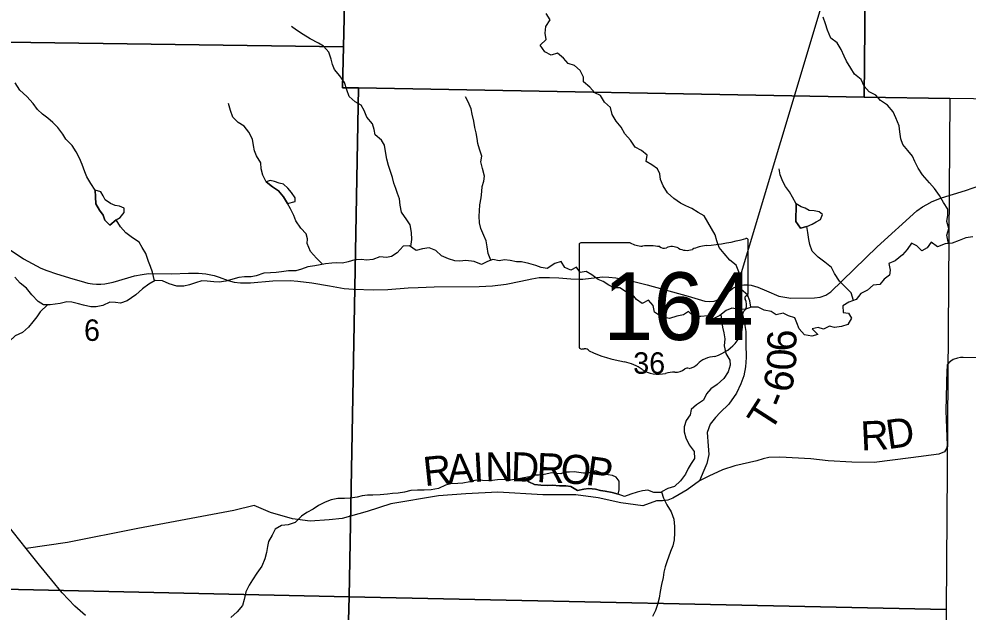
# Model space of a CAD drawing. Extents: x -3.6 to 34, y 0 to 32.8.
# Drawn here: x -0.41 to 1.441, y 27.961 to 29.117 of the extents above; entities that cross this region are included whole.
import ezdxf

# ---------------------------------------------------------------- set-up
doc = ezdxf.new("R2010")
doc.units = 0
for name, color, linetype in [('GM_X_Corporation', 7, 'Continuous'), ('GM_X_Minor_Lake', 7, 'Continuous'), ('GM_X_Minor_River', 7, 'Continuous'), ('GM_X_Section_Text', 7, 'Continuous'), ('GM_X_State_Location', 7, 'Continuous'), ('GM_X_State_Route', 7, 'Continuous'), ('GM_X_State_Shield', 7, 'Continuous'), ('GM_X_Township_Road', 7, 'Continuous'), ('GM_X_Township_Road_Text', 7, 'Continuous')]:
    doc.layers.add(name, color=color, linetype=linetype)

msp = doc.modelspace()

# ---------------------------------------------------------------- linework, layer by layer
at = {"layer": 'GM_X_Corporation'}
for points in [[(-0.7755, 30.0957), (0.2459, 30.0789), (0.244, 29.9924), (0.223, 29.0627), (-0.7627, 29.0764), (-0.7893, 29.0771)], [(1.2483, 29.9822), (1.2386, 28.9647), (0.2524, 28.9828), (0.2209, 28.9831), (0.223, 29.0627), (0.244, 29.9924)], [(2.2535, 29.9602), (2.2411, 28.9502), (1.4051, 28.9619), (1.2386, 28.9647), (1.2483, 29.9822)], [(-0.7627, 29.0764), (0.223, 29.0627), (0.2209, 28.9831), (0.2524, 28.9828), (0.2336, 27.9902), (-0.7925, 28.0131)], [(0.2524, 28.9828), (1.2386, 28.9647), (1.4051, 28.9619), (1.398, 27.966), (0.2336, 27.9902)], [(-0.7925, 28.0131), (0.2336, 27.9902), (0.2053, 26.9746), (-0.8131, 27.0015)], [(1.398, 27.966), (1.386, 26.9549), (0.2053, 26.9746), (0.2336, 27.9902)]]:
    msp.add_lwpolyline(points, close=True, dxfattribs=at)
at = {"layer": 'GM_X_Minor_Lake'}
for points in [[(0.1133, 28.7573), (0.1284, 28.7609), (0.1283, 28.7685), (0.1217, 28.779), (0.114, 28.7873), (0.1056, 28.7947), (0.0972, 28.7972), (0.0884, 28.8005), (0.0801, 28.8019), (0.0722, 28.7995)], [(-0.2617, 28.7834), (-0.2607, 28.7705), (-0.2605, 28.7565), (-0.2532, 28.7445), (-0.2458, 28.7347), (-0.2426, 28.7245), (-0.233, 28.7148), (-0.2203, 28.7253)], [(-0.2203, 28.7253), (-0.2128, 28.7303), (-0.2047, 28.7399), (-0.2052, 28.7479), (-0.2139, 28.7523), (-0.2227, 28.7537), (-0.2314, 28.757), (-0.2417, 28.7644), (-0.246, 28.7723), (-0.2507, 28.7798), (-0.2617, 28.7834)], [(0.0722, 28.7995), (0.0841, 28.7895), (0.0963, 28.7817), (0.1055, 28.7701), (0.1133, 28.7573)], [(1.1055, 28.7568), (1.1056, 28.7454), (1.1051, 28.7325), (1.1049, 28.7223), (1.1141, 28.7091), (1.1262, 28.7127)], [(1.1262, 28.7127), (1.1371, 28.7171), (1.145, 28.7214), (1.1529, 28.7264), (1.1573, 28.7356), (1.1507, 28.7408), (1.1405, 28.7433), (1.131, 28.7439), (1.123, 28.748), (1.1154, 28.7505), (1.1055, 28.7568)], [(0.7588, 28.1905), (0.7605, 28.1992), (0.7603, 28.2159), (0.7549, 28.2238), (0.7472, 28.2267), (0.7393, 28.2281), (0.7309, 28.2295), (0.7233, 28.2328), (0.7149, 28.2361), (0.7066, 28.2341), (0.6991, 28.2313), (0.6912, 28.2315), (0.6821, 28.2326), (0.673, 28.2339), (0.6639, 28.2334), (0.6548, 28.2333), (0.6465, 28.2301), (0.6386, 28.2311), (0.6291, 28.2321), (0.62, 28.2305), (0.6114, 28.2281), (0.6031, 28.2276), (0.594, 28.2278), (0.5857, 28.2246), (0.5744, 28.2226)], [(0.5744, 28.2226), (0.584, 28.2148), (0.5954, 28.2096), (0.6075, 28.2083), (0.62, 28.2077), (0.6306, 28.2079), (0.6442, 28.2066), (0.6567, 28.2071), (0.6662, 28.2058), (0.6792, 28.1976), (0.6913, 28.2004), (0.7015, 28.2014), (0.714, 28.2), (0.7238, 28.1975), (0.7333, 28.1965), (0.7466, 28.1937), (0.7588, 28.1905)]]:
    msp.add_lwpolyline(points, dxfattribs=at)
at = {"layer": 'GM_X_Minor_River'}
for points in [[(1.0172, 28.5549), (1.0156, 28.5673), (1.0109, 28.579), (0.9983, 28.5894), (0.9962, 28.6), (0.9945, 28.6133), (0.9936, 28.6239), (0.9885, 28.6371), (0.9766, 28.6471), (0.9654, 28.6595), (0.9558, 28.6715), (0.951, 28.6847), (0.9478, 28.696), (0.9408, 28.7088), (0.9335, 28.7208), (0.9261, 28.7332), (0.9143, 28.7395), (0.9024, 28.7473), (0.8902, 28.7528), (0.8803, 28.7579), (0.8673, 28.7672), (0.8546, 28.7784), (0.8465, 28.792), (0.8414, 28.8044), (0.8397, 28.8154), (0.8354, 28.8252), (0.8239, 28.8326), (0.8129, 28.8392), (0.8153, 28.8518), (0.8042, 28.8604), (0.7916, 28.8674), (0.7827, 28.8805), (0.7715, 28.8932), (0.7642, 28.906), (0.7549, 28.918), (0.7468, 28.9308), (0.7435, 28.9444), (0.732, 28.9548), (0.7239, 28.968), (0.7128, 28.9731), (0.7032, 28.984), (0.6909, 28.9944), (0.6908, 29.0039), (0.6841, 29.0163), (0.6734, 29.0264), (0.6612, 29.0304), (0.6516, 29.0405), (0.6401, 29.0502), (0.6281, 29.0462), (0.6158, 29.0532), (0.6062, 29.0663), (0.6178, 29.0771), (0.6164, 29.0893), (0.6174, 29.1022), (0.6259, 29.1156), (0.6181, 29.128)], [(1.4025, 28.6795), (1.3996, 28.6956), (1.4032, 28.7086), (1.3996, 28.7222), (1.4017, 28.7344), (1.4015, 28.7465), (1.393, 28.7593), (1.3852, 28.7728), (1.3752, 28.7863), (1.3659, 28.7979), (1.3521, 28.8129), (1.3436, 28.8264), (1.3373, 28.8392), (1.3326, 28.8498), (1.3237, 28.8606), (1.3137, 28.8726), (1.3098, 28.8832), (1.3077, 28.8972), (1.3064, 28.9085), (1.3004, 28.924), (1.2946, 28.9361), (1.2838, 28.9492), (1.2704, 28.9581), (1.2608, 28.9686), (1.2478, 28.9752), (1.2386, 28.986), (1.2323, 28.9989), (1.2193, 29.0097), (1.2123, 29.0213), (1.2038, 29.0345), (1.1995, 29.0443), (1.1936, 29.0578), (1.1854, 29.0706), (1.1732, 29.0799), (1.1669, 29.095), (1.1629, 29.1078), (1.1586, 29.1206)], [(0.3539, 28.6733), (0.3562, 28.6874), (0.3556, 28.701), (0.3527, 28.7154), (0.3461, 28.7256), (0.3357, 28.7406), (0.3332, 28.7538), (0.3319, 28.7667), (0.3279, 28.7765), (0.3248, 28.7863), (0.3212, 28.7969), (0.3184, 28.8078), (0.3152, 28.8176), (0.3108, 28.8312), (0.3072, 28.8437), (0.3048, 28.8584), (0.3027, 28.8709), (0.2968, 28.8807), (0.2846, 28.8911), (0.2829, 28.9017), (0.2793, 28.9127), (0.2685, 28.9258), (0.263, 28.9386), (0.2576, 28.9491), (0.2454, 28.9558), (0.2339, 28.9658), (0.2291, 28.9787), (0.2247, 28.993), (0.2155, 29.0065), (0.2054, 29.0185), (0.2015, 29.0283), (0.1987, 29.0385), (0.1943, 29.0525), (0.1835, 29.0641), (0.174, 29.0696), (0.1576, 29.0781), (0.1439, 29.0866), (0.1312, 29.0955), (0.1217, 29.1026)], [(-0.1456, 28.6063), (-0.1499, 28.6235), (-0.1539, 28.6345), (-0.1578, 28.6443), (-0.1629, 28.6598), (-0.1696, 28.6718), (-0.1754, 28.682), (-0.1888, 28.6905), (-0.2018, 28.7001), (-0.2122, 28.7121), (-0.2203, 28.7253), (-0.233, 28.7148), (-0.2426, 28.7245), (-0.2458, 28.7347), (-0.2532, 28.7445), (-0.2605, 28.7565), (-0.2607, 28.7705), (-0.2617, 28.7834), (-0.2699, 28.7966), (-0.278, 28.809), (-0.2819, 28.8188), (-0.2867, 28.8331), (-0.2922, 28.8459), (-0.2984, 28.858), (-0.3065, 28.8704), (-0.3185, 28.8827), (-0.3247, 28.8925), (-0.3343, 28.9056), (-0.3443, 28.9153), (-0.3539, 28.9235), (-0.3642, 28.9317), (-0.3742, 28.9406), (-0.3823, 28.9523), (-0.395, 28.9661), (-0.4085, 28.9781), (-0.4178, 28.9927)], [(0.182, 28.6388), (0.1702, 28.6508), (0.1586, 28.6639), (0.152, 28.679), (0.1526, 28.6885), (0.1502, 28.6983), (0.1398, 28.7095), (0.1301, 28.7234), (0.1258, 28.7336), (0.1195, 28.7471), (0.1133, 28.7573), (0.1055, 28.7701), (0.0963, 28.7817), (0.0841, 28.7895), (0.0722, 28.7995), (0.0652, 28.8127), (0.0623, 28.8252), (0.0614, 28.8369), (0.0532, 28.8501), (0.0493, 28.8602), (0.0476, 28.8705), (0.0456, 28.8829), (0.0382, 28.8961), (0.0293, 28.9081), (0.0171, 28.9155), (0.0067, 28.9256), (0.0023, 28.9384), (-0.0017, 28.9524)], [(0.51, 28.6465), (0.5053, 28.6601), (0.5028, 28.6726), (0.5008, 28.6843), (0.4968, 28.6952), (0.4909, 28.7088), (0.4881, 28.7197), (0.4875, 28.7326), (0.4881, 28.7429), (0.4887, 28.7547), (0.4915, 28.7684), (0.4925, 28.7809), (0.4935, 28.7904), (0.4963, 28.801), (0.4981, 28.8109), (0.4941, 28.8257), (0.4908, 28.8385), (0.4926, 28.8495), (0.4878, 28.8631), (0.4846, 28.8741), (0.4833, 28.8843), (0.4817, 28.8949), (0.4792, 28.9055), (0.4772, 28.9176), (0.4739, 28.9312), (0.4715, 28.9418), (0.466, 28.9553), (0.4605, 28.9651)], [(1.2174, 28.5682), (1.2129, 28.5828), (1.2025, 28.5936), (1.1899, 28.606), (1.1806, 28.6206), (1.1743, 28.6327), (1.1613, 28.6427), (1.1483, 28.6524), (1.1368, 28.6643), (1.1324, 28.6776), (1.1304, 28.6874), (1.1286, 28.701), (1.1262, 28.7127), (1.1141, 28.7091), (1.1049, 28.7223), (1.1051, 28.7325), (1.1056, 28.7454), (1.1055, 28.7568), (1.0988, 28.7696), (1.093, 28.7798), (1.0849, 28.7903), (1.0798, 28.8004), (1.0747, 28.8132), (1.0723, 28.8246)], [(1.4504, 28.6926), (1.4368, 28.6905), (1.4233, 28.685), (1.4097, 28.6802), (1.3961, 28.6789), (1.3815, 28.673), (1.3688, 28.6819), (1.3614, 28.6711), (1.3505, 28.6649), (1.3413, 28.6746), (1.3306, 28.6798)], [(1.3306, 28.6798), (1.3225, 28.6679), (1.3132, 28.6571), (1.2986, 28.6455), (1.2866, 28.6404), (1.2891, 28.6276), (1.2877, 28.6173), (1.2776, 28.6099), (1.2687, 28.5992), (1.2558, 28.5982), (1.245, 28.5886), (1.2319, 28.5819), (1.2226, 28.57), (1.2083, 28.5649), (1.197, 28.5575), (1.1976, 28.545), (1.2075, 28.5433), (1.2133, 28.5335), (1.2067, 28.5212), (1.1939, 28.5172), (1.1807, 28.5152), (1.1704, 28.518), (1.1588, 28.5125), (1.1489, 28.5158), (1.1368, 28.5126), (1.1479, 28.5021), (1.1363, 28.4985), (1.1218, 28.5014), (1.1118, 28.513), (1.1071, 28.5247), (1.1032, 28.5345), (1.0906, 28.5385), (1.0803, 28.5436), (1.0668, 28.5404), (1.0568, 28.547), (1.0435, 28.5491), (1.0313, 28.5554), (1.0181, 28.5552), (1.0057, 28.5504), (0.9928, 28.5514), (0.9799, 28.5531), (0.9694, 28.5488), (0.9567, 28.5391), (0.9435, 28.5321), (0.9336, 28.538), (0.92, 28.537), (0.9064, 28.5372), (0.8956, 28.5469), (0.8859, 28.5403), (0.8727, 28.5378), (0.8588, 28.533), (0.8432, 28.5366), (0.8294, 28.5455), (0.827, 28.5587), (0.8177, 28.5688), (0.8053, 28.5622), (0.7946, 28.5704), (0.7865, 28.5801), (0.7728, 28.5856), (0.7617, 28.593), (0.75, 28.5929), (0.7401, 28.598), (0.7294, 28.6054), (0.7195, 28.6091), (0.7069, 28.6184), (0.6962, 28.625), (0.6841, 28.623), (0.6775, 28.6331), (0.6659, 28.6276), (0.6544, 28.6324), (0.6471, 28.6444), (0.635, 28.6404), (0.62, 28.6307), (0.6083, 28.6328), (0.598, 28.6361), (0.5843, 28.64), (0.5699, 28.6436), (0.56, 28.6435), (0.5479, 28.6463), (0.5369, 28.6473), (0.5267, 28.6452), (0.5138, 28.6481), (0.504, 28.6441), (0.492, 28.6382), (0.4779, 28.6445), (0.4612, 28.6461), (0.4495, 28.6448), (0.4401, 28.6458), (0.4275, 28.6494), (0.4142, 28.6553), (0.4027, 28.6657), (0.3901, 28.6708), (0.3769, 28.6687), (0.3645, 28.6655), (0.3518, 28.6748), (0.3394, 28.6739), (0.3278, 28.6612), (0.3166, 28.6538), (0.3064, 28.6521), (0.2935, 28.6531), (0.2803, 28.6479)], [(0.2803, 28.6479), (0.2675, 28.647), (0.258, 28.648), (0.2448, 28.6474), (0.232, 28.6434), (0.221, 28.641), (0.2101, 28.6415), (0.2002, 28.641), (0.1874, 28.6397), (0.1776, 28.638), (0.1666, 28.636), (0.153, 28.6335), (0.1406, 28.6295), (0.1297, 28.6263), (0.1157, 28.6257), (0.1017, 28.6243), (0.0915, 28.6227), (0.0806, 28.6221), (0.0673, 28.6215), (0.0527, 28.616), (0.0428, 28.6143), (0.0296, 28.6145), (0.019, 28.6128), (-0.0066, 28.606), (-0.0198, 28.6039), (-0.03, 28.6045), (-0.0433, 28.6058), (-0.0535, 28.6068), (-0.066, 28.6024), (-0.0776, 28.5988), (-0.0886, 28.5964), (-0.1022, 28.5958), (-0.117, 28.6009), (-0.13, 28.6064), (-0.1444, 28.6069), (-0.1567, 28.5999), (-0.1691, 28.5906), (-0.1825, 28.5794), (-0.199, 28.5678), (-0.2122, 28.563), (-0.222, 28.564), (-0.2326, 28.5646), (-0.2465, 28.5583), (-0.2594, 28.5555), (-0.27, 28.5557), (-0.2844, 28.5593), (-0.2939, 28.5618), (-0.3072, 28.5646), (-0.3167, 28.5656), (-0.3295, 28.5624), (-0.3491, 28.5598), (-0.362, 28.56), (-0.3727, 28.5659), (-0.385, 28.579), (-0.3954, 28.5925), (-0.4076, 28.6018), (-0.418, 28.6134)], [(-0.3547, 28.5599), (-0.3686, 28.5462), (-0.3756, 28.5363), (-0.383, 28.5267), (-0.3916, 28.5159), (-0.4035, 28.5055), (-0.4178, 28.4992), (-0.4294, 28.4884), (-0.4341, 28.4777), (-0.4408, 28.4651), (-0.4538, 28.4535), (-0.4627, 28.4435), (-0.4694, 28.4332), (-0.4813, 28.4209), (-0.4887, 28.4094), (-0.5002, 28.3959), (-0.5123, 28.3904), (-0.5248, 28.3952), (-0.5391, 28.3877), (-0.5523, 28.386), (-0.566, 28.3919), (-0.5794, 28.3996)], [(0.959, 28.5408), (0.9598, 28.5296), (0.9623, 28.5164), (0.9644, 28.5054), (0.9664, 28.4937), (0.9655, 28.4797), (0.9688, 28.4649), (0.9762, 28.4517), (0.9771, 28.4423), (0.9731, 28.4293), (0.9646, 28.4159), (0.9519, 28.4043), (0.9395, 28.3962), (0.9306, 28.3862), (0.9251, 28.3736), (0.9113, 28.365), (0.9012, 28.3554), (0.8987, 28.3451), (0.8909, 28.3344), (0.8873, 28.3218), (0.8871, 28.3123), (0.8907, 28.3002), (0.8969, 28.2866), (0.9066, 28.2735), (0.9075, 28.2599), (0.9009, 28.2503), (0.895, 28.2403), (0.8898, 28.2296), (0.8798, 28.2166), (0.8683, 28.2058), (0.8555, 28.2018), (0.8431, 28.1948), (0.847, 28.1827), (0.8533, 28.1695), (0.8618, 28.1564), (0.867, 28.1416), (0.8687, 28.1272), (0.8681, 28.1151), (0.8676, 28.1014), (0.8651, 28.09), (0.8607, 28.0789), (0.8535, 28.0583), (0.8502, 28.0488), (0.8477, 28.0385), (0.8463, 28.0282), (0.8428, 28.0142), (0.8403, 28.0005), (0.8382, 27.9879), (0.835, 27.9757), (0.8314, 27.9639), (0.8255, 27.952)], [(0.8433, 28.194), (0.828, 28.1938), (0.8162, 28.1985), (0.8063, 28.1969), (0.7954, 28.1944), (0.783, 28.1904), (0.7706, 28.1861), (0.7588, 28.1905), (0.7466, 28.1937), (0.7333, 28.1965), (0.7238, 28.1975), (0.714, 28.2), (0.7015, 28.2014), (0.6913, 28.2004), (0.6792, 28.1976), (0.6662, 28.2058), (0.6567, 28.2071), (0.6442, 28.2066), (0.6306, 28.2079), (0.62, 28.2077), (0.6075, 28.2083), (0.5954, 28.2096), (0.584, 28.2148), (0.5744, 28.2226), (0.5608, 28.2197), (0.5483, 28.2176), (0.5366, 28.219), (0.5234, 28.2184), (0.5083, 28.2166), (0.4942, 28.2172), (0.4817, 28.2181), (0.4689, 28.2149), (0.4557, 28.2117), (0.4459, 28.2111), (0.4319, 28.2109), (0.4217, 28.2081), (0.4078, 28.2018), (0.3935, 28.1993), (0.3803, 28.1984), (0.3674, 28.1982), (0.3542, 28.1976), (0.3421, 28.1944), (0.3293, 28.1923), (0.3183, 28.1921), (0.3085, 28.1908), (0.2941, 28.1895), (0.2798, 28.1885), (0.2699, 28.1884), (0.259, 28.1871), (0.2492, 28.185), (0.2359, 28.1829), (0.2246, 28.1824), (0.2117, 28.1822), (0.1985, 28.1797), (0.1873, 28.175), (0.1741, 28.1687), (0.1636, 28.1613), (0.1516, 28.1551), (0.1411, 28.1477), (0.1285, 28.135), (0.1149, 28.1306), (0.102, 28.1297), (0.0893, 28.1223), (0.0834, 28.1108), (0.0768, 28.0982), (0.0743, 28.0886), (0.0729, 28.0769), (0.0694, 28.0647), (0.0635, 28.0502), (0.0539, 28.0367), (0.0454, 28.0237), (0.0391, 28.013), (0.0325, 28), (0.0293, 27.9851), (0.0257, 27.9733), (0.0153, 27.961), (0.0033, 27.9502)]]:
    msp.add_lwpolyline(points, dxfattribs=at)
at = {"layer": 'GM_X_State_Route'}
for points in [[(-0.4635, 28.6907), (-0.4014, 28.6497), (-0.3675, 28.6314), (-0.3555, 28.6267), (-0.3367, 28.6203), (-0.3049, 28.6106), (-0.2934, 28.6074), (-0.2824, 28.6038), (-0.2759, 28.6018), (-0.267, 28.6005), (-0.2589, 28.5998), (-0.2506, 28.5997), (-0.2425, 28.6008), (-0.2261, 28.6037), (-0.1977, 28.6125), (-0.1846, 28.6161), (-0.1701, 28.619), (-0.1573, 28.6211), (-0.1129, 28.6202), (-0.0793, 28.6215), (-0.06, 28.6213), (-0.0458, 28.62), (-0.0295, 28.617), (-0.0194, 28.6135), (-0.0019, 28.6071), (0.0097, 28.6037), (0.0218, 28.6027), (0.0412, 28.6028), (0.0848, 28.6068), (0.1185, 28.6072), (0.134, 28.6059), (0.1613, 28.6028), (0.1953, 28.5965), (0.2239, 28.5916), (0.2426, 28.59), (0.2821, 28.5888), (0.3094, 28.5895), (0.3487, 28.5926), (0.3684, 28.5932), (0.3995, 28.5948), (0.4877, 28.5957), (0.5134, 28.5968), (0.5399, 28.5999), (0.5689, 28.6061), (0.5902, 28.6107), (0.6043, 28.6129), (0.6243, 28.6129), (0.6426, 28.6125), (0.6663, 28.6107), (0.6818, 28.6099), (0.6899, 28.6098), (0.7277, 28.6144), (0.7401, 28.6139), (0.754, 28.6125), (0.7838, 28.6068), (0.8151, 28.5989), (0.8952, 28.5765), (0.9275, 28.5668), (0.9362, 28.5659), (0.9458, 28.5668), (0.955, 28.57), (0.9821, 28.5921), (0.9908, 28.596), (0.9975, 28.5979), (1.0037, 28.5988), (1.0125, 28.5985), (1.0177, 28.5979), (1.0243, 28.596), (1.031, 28.5939), (1.0481, 28.5868), (1.0722, 28.5767), (1.0955, 28.5726), (1.1416, 28.5731), (1.1526, 28.5746), (1.1636, 28.5786), (1.173, 28.5852), (1.2639, 28.6726), (1.3412, 28.743), (1.3523, 28.7509), (1.3603, 28.7556), (1.3711, 28.7611), (1.389, 28.7684), (1.436, 28.7827), (1.4658, 28.7929)], [(-0.2804, 27.954), (-0.3014, 27.972), (-0.3258, 27.998), (-0.3462, 28.023), (-0.3704, 28.0521), (-0.3962, 28.0843), (-0.4332, 28.1316)]]:
    msp.add_lwpolyline(points, dxfattribs=at)
at = {"layer": 'GM_X_State_Shield'}
for p, q in [((0.6824, 28.6772), (0.6824, 28.4771)), ((0.7822, 28.6807), (0.6857, 28.6807)), ((1.012, 28.5809), (1.012, 28.6856)), ((1.012, 28.581), (1.012, 28.5809))]:
    msp.add_line(p, q, dxfattribs=at)
for centre, major_axis, start_param, end_param in [((0.6862, 28.6776), (0.00382, 0), 1.712693, 3.28349), ((0.8052, 28.7039), (0.037, 0), 4.042523, 4.731795), ((0.8175, 28.5683), (0.133, 0), 1.404758, 1.657858), ((0.8476, 28.6787), (0.0107, 0), 3.836095, 5.185415), ((0.8633, 28.6556), (0.0222, 0), 0.950623, 2.079405), ((0.9392, 28.6195), (0.0703, 0), 1.699011, 2.107814), ((0.8946, 28.9535), (0.3495, 0), 4.814394, 5.042369), ((1.0083, 28.6861), (0.00367, 0), 6.141152, 7.989035), ((0.892, 28.6873), (0.0267, 0), 4.081561, 5.145723), ((1.0081, 28.5805), (0.00393, 0), 5.05454, 6.418171), ((1.0112, 28.5733), (0.00568, 0), 1.883978, 3.671073), ((0.975, 28.56), (0.0341, 0), 5.934695, 6.695948), ((1.0251, 28.5371), (0.0248, 0), 2.387724, 3.262537), ((0.9142, 28.5238), (0.0874, 0), 5.101752, 6.440018), ((0.6862, 28.4767), (0.00385, 0), 3.00124, 4.508301), ((0.6868, 28.4971), (0.0294, 0), 4.665946, 4.897461), ((0.6928, 28.4656), (0.0106, 0), 0.519207, 1.627899), ((0.8267, 28.6454), (0.2524, 0), 4.195997, 4.488961), ((0.951, 28.4209), (0.0479, 0), 1.647645, 2.488434), ((0.7514, 28.3872), (0.079, 0), 0.823519, 1.323587), ((0.8368, 28.4646), (0.0501, 0), 4.026481, 4.996735), ((0.8694, 28.4496), (0.0267, 0), 4.691044, 5.507374), ((0.8936, 28.4302), (0.00752, 0), 1.147584, 2.315152), ((0.8904, 28.4577), (0.0282, 0), 4.937069, 5.64225), ((0.8658, 28.3954), (0.0412, 0), 1.495662, 1.94098)]:
    msp.add_ellipse(centre, major_axis=major_axis, ratio=0.8, start_param=start_param, end_param=end_param, dxfattribs=at)
at = {"layer": 'GM_X_Township_Road'}
msp.add_line((1.2353, 29.4101), (0.9908, 28.596), dxfattribs=at)
for points in [[(0.9908, 28.596), (0.9925, 28.5812), (0.9999, 28.5463), (1.0041, 28.5271), (1.0077, 28.5077), (1.0075, 28.4838), (1.0081, 28.4573), (1.0069, 28.4388), (1.0035, 28.4216), (0.9979, 28.4059), (0.9893, 28.3874), (0.9742, 28.3661), (0.9572, 28.3495), (0.9485, 28.3403), (0.938, 28.327), (0.9319, 28.3107), (0.9339, 28.2846), (0.9351, 28.2676), (0.9317, 28.2506), (0.9259, 28.2368), (0.9174, 28.2164)], [(1.5099, 28.4565), (1.4317, 28.4572), (1.4259, 28.4571), (1.4203, 28.4558), (1.4122, 28.4529), (1.4071, 28.4499), (1.4032, 28.4464), (1.4005, 28.4426), (1.3999, 28.4375), (1.3994, 28.4327), (1.3973, 28.3529), (1.4002, 28.2856), (1.3991, 28.2793), (1.3947, 28.2728), (1.3842, 28.2686), (1.3295, 28.2612), (1.2578, 28.2523), (1.214, 28.2528), (1.1684, 28.2558), (1.1343, 28.2592), (1.0739, 28.263), (1.0522, 28.2621), (1.0411, 28.2592), (1.0287, 28.2555), (0.9862, 28.2458), (0.9622, 28.238), (0.9354, 28.2256), (0.9174, 28.2164)], [(0.9174, 28.2164), (0.8929, 28.1992), (0.8777, 28.1896), (0.8652, 28.1829), (0.8552, 28.179), (0.8447, 28.1777), (0.833, 28.1775), (0.8067, 28.168), (0.7636, 28.1738), (0.7196, 28.1831), (0.6761, 28.1894), (0.6119, 28.1891), (0.5239, 28.1947), (0.4616, 28.191), (0.4084, 28.1875), (0.3152, 28.1717), (0.2691, 28.157), (0.22, 28.1433), (0.1949, 28.1408), (0.1581, 28.1377), (0.1234, 28.1427), (0.0805, 28.155), (0.0486, 28.1687), (0.0089, 28.1587), (-0.1782, 28.1236), (-0.3153, 28.0966), (-0.3962, 28.0843)]]:
    msp.add_lwpolyline(points, dxfattribs=at)

# ---------------------------------------------------------------- texts
at = {"layer": 'GM_X_Section_Text'}
for s, height, p in [('6', 0.0419, (-0.2833, 28.4894)), ('36', 0.04186, (0.7879, 28.4253))]:
    msp.add_text(s, height=height, rotation=0, dxfattribs=at).set_placement(p)
at = {"layer": 'GM_X_State_Location'}
for s in ['s', 'r']:
    msp.add_text(s, height=0.000189, dxfattribs=at).set_placement((0.8435, 28.5639))
msp.add_text('164', height=0.000189, rotation=0, dxfattribs=at).set_placement((0.7767, 28.5501))
at = {"layer": 'GM_X_State_Shield'}
msp.add_text('164', height=0.13184, dxfattribs=at).set_placement((0.7289, 28.4912))
at = {"layer": 'GM_X_Township_Road_Text'}
for s, rotation, p in [('6', 90.8275, (1.1066, 28.4695)), ('0', 86.8112, (1.1046, 28.4305)), ('6', 76.4375, (1.0948, 28.3856)), ('T', 57.2942, (1.055, 28.3096)), ('-', 67.6515, (1.0831, 28.3552)), ('D', 7.9356, (1.2849, 28.2782)), ('R', 2.6999, (1.2327, 28.2755)), ('R', 5.9863, (0.3813, 28.206)), ('A', 3.7822, (0.4271, 28.2108)), ('I', 3.2647, (0.4769, 28.2141)), ('N', 0.6229, (0.4995, 28.2154)), ('D', 358.0635, (0.5488, 28.216)), ('R', 357.7377, (0.5987, 28.2143)), ('O', 356.0408, (0.6449, 28.2125)), ('P', 351.8094, (0.6936, 28.2091))]:
    msp.add_text(s, height=0.0568, rotation=rotation, dxfattribs=at).set_placement(p)

doc.saveas('drawing.dxf')
